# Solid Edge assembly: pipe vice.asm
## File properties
Author: CADCIM
Template: Iso Assembly.asm
Last saved by: Rajat Kamboj
Revision: 4
Application: Solid Edge
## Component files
base.par
Screw.par
moveable jaw.par
handle.par
handle screw.par
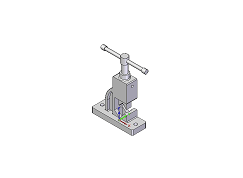
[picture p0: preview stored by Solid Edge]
